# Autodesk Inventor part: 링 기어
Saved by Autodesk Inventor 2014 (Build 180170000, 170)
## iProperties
Created: 2026-05
Part Number: 링 기어
Material: 일반
Document SubType Name: Modeling
Designer: dg
Density: 1 g/cm^3
Appearance: 기본값
Author: dg
Author: jhkim
Creation Date: 2026-04-27
Sending System: Autodesk Inventor 2027
Preprocessor: ST-DEVELOPER v20.1
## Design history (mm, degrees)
node "링 기어1"
node "솔리드1"
node "기준1"
